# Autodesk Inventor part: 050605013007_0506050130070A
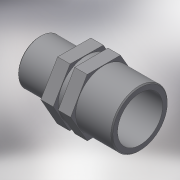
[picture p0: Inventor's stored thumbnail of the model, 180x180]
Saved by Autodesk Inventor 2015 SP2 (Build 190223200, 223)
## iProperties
Created: 2017-05
Part Number: 050605013007_0506050130070A
Material: Generic
Description: PLASSON REDUCING NIPPLE 1.1/4"-3/4"
Document SubType Name: Modeling
Designer: KIM
Density: 1 g/cm^3
Appearance: Default
Author: KIM
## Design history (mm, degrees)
derived "050605.ipt"
feature "Solid1::050605.ipt"
tag "TaggingFeature1"
body "Solid1"
other parameters: "d0" = 54, "d1" = 41.91, "d5" = 21, "d6" = 5.4, "d8" = 0.54, "d12" = 0, "d14" = 26.441, "d15" = 21.1528, "d16" = 33.528, "d17" = 17, "d18" = 2.7, "d19" = 46, "d21" = 0, "H_" = 54, "R_" = 41.91, "E_" = 46, "l_" = 21, "R_1" = 26.441, "l_1" = 17
